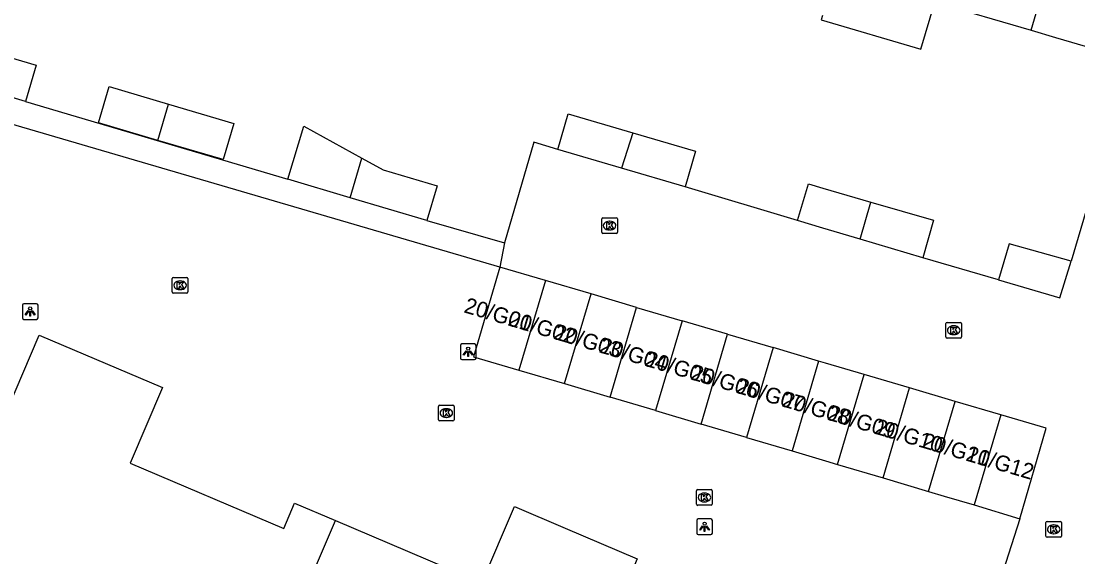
# Model space of a CAD drawing. Extents: x 161771 to 163125, y 382479 to 383177.
# Drawn here: x 162448.9 to 162516.2, y 382553 to 382587.1 of the extents above; entities that cross this region are included whole.
import ezdxf

# ---------------------------------------------------------------- set-up
doc = ezdxf.new("R2010")
doc.units = 0
for name, color, linetype in [('IMGEO_Kolk', 7, 'Continuous'), ('IMGEO_Lichtpunt', 7, 'Continuous'), ('IMGEO_Pand', 7, 'Continuous'), ('IMGEO_Pand_nummerreeks', 7, 'Continuous'), ('IMGEO_Voetpad_open', 7, 'Continuous')]:
    doc.layers.add(name, color=color, linetype=linetype)

msp = doc.modelspace()

# ---------------------------------------------------------------- linework, layer by layer
at = {"layer": 'IMGEO_Kolk'}
for p, q in [((162485.92, 382573.655), (162485.92, 382574.507)), ((162485.995, 382574.581), (162486.847, 382574.581)), ((162486.408, 382574.361), (162486.433, 382574.361)), ((162486.921, 382574.507), (162486.921, 382573.655)), ((162486.847, 382573.581), (162485.995, 382573.581)), ((162486.431, 382573.801), (162486.406, 382573.801)), ((162458.569, 382569.851), (162458.569, 382570.703)), ((162458.644, 382570.777), (162459.496, 382570.777)), ((162459.57, 382570.703), (162459.57, 382569.851)), ((162459.057, 382570.557), (162459.082, 382570.557)), ((162459.496, 382569.777), (162458.644, 382569.777)), ((162459.08, 382569.997), (162459.055, 382569.997)), ((162507.84, 382566.985), (162507.84, 382567.837)), ((162507.915, 382567.911), (162508.767, 382567.911)), ((162508.328, 382567.691), (162508.353, 382567.691)), ((162508.841, 382567.837), (162508.841, 382566.985)), ((162508.767, 382566.911), (162507.915, 382566.911)), ((162508.351, 382567.131), (162508.326, 382567.131)), ((162475.597, 382562.631), (162476.449, 382562.631)), ((162475.522, 382561.705), (162475.522, 382562.557)), ((162476.01, 382562.411), (162476.035, 382562.411)), ((162476.523, 382562.557), (162476.523, 382561.705)), ((162476.449, 382561.631), (162475.597, 382561.631)), ((162476.033, 382561.851), (162476.008, 382561.851)), ((162492.037, 382557.25), (162492.889, 382557.25)), ((162491.962, 382556.324), (162491.962, 382557.176)), ((162492.45, 382557.03), (162492.475, 382557.03)), ((162492.963, 382557.176), (162492.963, 382556.324)), ((162492.889, 382556.25), (162492.037, 382556.25)), ((162492.473, 382556.47), (162492.448, 382556.47)), ((162514.284, 382555.221), (162515.136, 382555.221)), ((162514.209, 382554.295), (162514.209, 382555.147)), ((162514.697, 382555.001), (162514.722, 382555.001)), ((162515.21, 382555.147), (162515.21, 382554.295)), ((162515.136, 382554.221), (162514.284, 382554.221)), ((162514.72, 382554.441), (162514.695, 382554.441))]:
    msp.add_line(p, q, dxfattribs=at)
for points in [[(162485.92, 382573.655), (162485.92, 382574.507)], [(162485.995, 382574.581), (162486.847, 382574.581)], [(162486.241, 382574.281), (162486.364, 382574.281), (162486.364, 382574.13), (162486.494, 382574.281), (162486.658, 382574.281), (162486.512, 382574.13), (162486.665, 382573.881), (162486.513, 382573.881), (162486.428, 382574.045), (162486.364, 382573.978), (162486.364, 382573.881), (162486.241, 382573.881), (162486.241, 382574.281)], [(162486.921, 382574.507), (162486.921, 382573.655)], [(162486.847, 382573.581), (162485.995, 382573.581)], [(162458.569, 382569.851), (162458.569, 382570.703)], [(162458.644, 382570.777), (162459.496, 382570.777)], [(162459.57, 382570.703), (162459.57, 382569.851)], [(162458.89, 382570.477), (162459.013, 382570.477), (162459.013, 382570.326), (162459.143, 382570.477), (162459.307, 382570.477), (162459.161, 382570.326), (162459.314, 382570.077), (162459.162, 382570.077), (162459.077, 382570.241), (162459.013, 382570.174), (162459.013, 382570.077), (162458.89, 382570.077), (162458.89, 382570.477)], [(162459.496, 382569.777), (162458.644, 382569.777)], [(162507.84, 382566.985), (162507.84, 382567.837)], [(162507.915, 382567.911), (162508.767, 382567.911)], [(162508.161, 382567.611), (162508.284, 382567.611), (162508.284, 382567.46), (162508.414, 382567.611), (162508.578, 382567.611), (162508.432, 382567.46), (162508.585, 382567.211), (162508.433, 382567.211), (162508.348, 382567.375), (162508.284, 382567.308), (162508.284, 382567.211), (162508.161, 382567.211), (162508.161, 382567.611)], [(162508.841, 382567.837), (162508.841, 382566.985)], [(162508.767, 382566.911), (162507.915, 382566.911)], [(162475.597, 382562.631), (162476.449, 382562.631)], [(162475.522, 382561.705), (162475.522, 382562.557)], [(162475.843, 382562.331), (162475.966, 382562.331), (162475.966, 382562.18), (162476.096, 382562.331), (162476.26, 382562.331), (162476.114, 382562.18), (162476.267, 382561.931), (162476.115, 382561.931), (162476.03, 382562.095), (162475.966, 382562.028), (162475.966, 382561.931), (162475.843, 382561.931), (162475.843, 382562.331)], [(162476.523, 382562.557), (162476.523, 382561.705)], [(162476.449, 382561.631), (162475.597, 382561.631)], [(162492.037, 382557.25), (162492.889, 382557.25)], [(162491.962, 382556.324), (162491.962, 382557.176)], [(162492.283, 382556.95), (162492.406, 382556.95), (162492.406, 382556.799), (162492.536, 382556.95), (162492.7, 382556.95), (162492.554, 382556.799), (162492.707, 382556.55), (162492.555, 382556.55), (162492.47, 382556.714), (162492.406, 382556.647), (162492.406, 382556.55), (162492.283, 382556.55), (162492.283, 382556.95)], [(162492.963, 382557.176), (162492.963, 382556.324)], [(162492.889, 382556.25), (162492.037, 382556.25)], [(162514.284, 382555.221), (162515.136, 382555.221)], [(162514.209, 382554.295), (162514.209, 382555.147)], [(162514.53, 382554.921), (162514.653, 382554.921), (162514.653, 382554.77), (162514.783, 382554.921), (162514.947, 382554.921), (162514.801, 382554.77), (162514.954, 382554.521), (162514.802, 382554.521), (162514.717, 382554.685), (162514.653, 382554.618), (162514.653, 382554.521), (162514.53, 382554.521), (162514.53, 382554.921)], [(162515.21, 382555.147), (162515.21, 382554.295)], [(162515.136, 382554.221), (162514.284, 382554.221)]]:
    msp.add_lwpolyline(points, dxfattribs=at)
for centre, start, end in [((162485.997, 382574.505), 91.55205, 178.44795), ((162485.997, 382574.505), 91.55205, 178.44795), ((162486.845, 382574.505), 1.55205, 88.44795), ((162486.845, 382574.505), 1.55205, 88.44795), ((162485.997, 382573.657), 181.55205, 268.44795), ((162485.997, 382573.657), 181.55205, 268.44795), ((162486.845, 382573.657), 271.55205, 358.44795), ((162486.845, 382573.657), 271.55205, 358.44795), ((162458.646, 382570.701), 91.55205, 178.44795), ((162458.646, 382570.701), 91.55205, 178.44795), ((162459.494, 382570.701), 1.55205, 88.44795), ((162459.494, 382570.701), 1.55205, 88.44795), ((162458.646, 382569.853), 181.55205, 268.44795), ((162458.646, 382569.853), 181.55205, 268.44795), ((162459.494, 382569.853), 271.55205, 358.44795), ((162459.494, 382569.853), 271.55205, 358.44795), ((162507.917, 382567.835), 91.55205, 178.44795), ((162507.917, 382567.835), 91.55205, 178.44795), ((162508.765, 382567.835), 1.55205, 88.44795), ((162508.765, 382567.835), 1.55205, 88.44795), ((162507.917, 382566.987), 181.55205, 268.44795), ((162507.917, 382566.987), 181.55205, 268.44795), ((162508.765, 382566.987), 271.55205, 358.44795), ((162508.765, 382566.987), 271.55205, 358.44795), ((162475.599, 382562.555), 91.55205, 178.44795), ((162475.599, 382562.555), 91.55205, 178.44795), ((162476.447, 382562.555), 1.55205, 88.44795), ((162476.447, 382562.555), 1.55205, 88.44795), ((162475.599, 382561.707), 181.55205, 268.44795), ((162475.599, 382561.707), 181.55205, 268.44795), ((162476.447, 382561.707), 271.55205, 358.44795), ((162476.447, 382561.707), 271.55205, 358.44795), ((162492.039, 382557.174), 91.55205, 178.44795), ((162492.039, 382557.174), 91.55205, 178.44795), ((162492.887, 382557.174), 1.55205, 88.44795), ((162492.887, 382557.174), 1.55205, 88.44795), ((162492.039, 382556.326), 181.55205, 268.44795), ((162492.039, 382556.326), 181.55205, 268.44795), ((162492.887, 382556.326), 271.55205, 358.44795), ((162492.887, 382556.326), 271.55205, 358.44795), ((162514.286, 382555.145), 91.55205, 178.44795), ((162514.286, 382555.145), 91.55205, 178.44795), ((162515.134, 382555.145), 1.55205, 88.44795), ((162515.134, 382555.145), 1.55205, 88.44795), ((162514.286, 382554.297), 181.55205, 268.44795), ((162514.286, 382554.297), 181.55205, 268.44795), ((162515.134, 382554.297), 271.55205, 358.44795), ((162515.134, 382554.297), 271.55205, 358.44795)]:
    msp.add_arc(centre, 0.0765, start, end, dxfattribs=at)
for centre, major_axis, ratio, start_param, end_param in [((162486.407, 382574.081), (-0.387, 0.002), 0.722429, 4.712389, 7.853982), ((162486.432, 382574.081), (-0.39, 0.002), 0.717154, 1.570796, 4.712389), ((162459.056, 382570.277), (-0.387, 0.002), 0.722429, 4.712389, 7.853982), ((162459.081, 382570.277), (-0.39, 0.002), 0.717154, 1.570796, 4.712389), ((162508.327, 382567.411), (-0.387, 0.002), 0.722429, 4.712389, 7.853982), ((162508.352, 382567.411), (-0.39, 0.002), 0.717154, 1.570796, 4.712389), ((162476.009, 382562.131), (-0.387, 0.002), 0.722429, 4.712389, 7.853982), ((162476.034, 382562.131), (-0.39, 0.002), 0.717154, 1.570796, 4.712389), ((162492.449, 382556.75), (-0.387, 0.002), 0.722429, 4.712389, 7.853982), ((162492.474, 382556.75), (-0.39, 0.002), 0.717154, 1.570796, 4.712389), ((162514.696, 382554.721), (-0.387, 0.002), 0.722429, 4.712389, 7.853982), ((162514.721, 382554.721), (-0.39, 0.002), 0.717154, 1.570796, 4.712389)]:
    msp.add_ellipse(centre, major_axis=major_axis, ratio=ratio, start_param=start_param, end_param=end_param, dxfattribs=at)
at = {"layer": 'IMGEO_Lichtpunt'}
for p, q in [((162449.023, 382569.006), (162449.023, 382568.199)), ((162449.023, 382569.006), (162449.023, 382568.199)), ((162449.925, 382569.101), (162449.117, 382569.101)), ((162449.925, 382569.101), (162449.117, 382569.101)), ((162450.019, 382568.199), (162450.019, 382569.006)), ((162450.019, 382568.199), (162450.019, 382569.006)), ((162449.117, 382568.105), (162449.925, 382568.105)), ((162449.117, 382568.105), (162449.925, 382568.105)), ((162476.92, 382566.441), (162476.92, 382565.634)), ((162476.92, 382566.441), (162476.92, 382565.634)), ((162477.822, 382566.536), (162477.014, 382566.536)), ((162477.822, 382566.536), (162477.014, 382566.536)), ((162477.916, 382565.634), (162477.916, 382566.441)), ((162477.916, 382565.634), (162477.916, 382566.441)), ((162477.014, 382565.54), (162477.822, 382565.54)), ((162477.014, 382565.54), (162477.822, 382565.54)), ((162491.972, 382555.287), (162491.972, 382554.48)), ((162491.972, 382555.287), (162491.972, 382554.48)), ((162492.874, 382555.382), (162492.066, 382555.382)), ((162492.874, 382555.382), (162492.066, 382555.382)), ((162492.968, 382554.48), (162492.968, 382555.287)), ((162492.968, 382554.48), (162492.968, 382555.287)), ((162492.066, 382554.386), (162492.874, 382554.386)), ((162492.066, 382554.386), (162492.874, 382554.386))]:
    msp.add_line(p, q, dxfattribs=at)
for points in [[(162449.397, 382568.67), (162449.436, 382568.642), (162449.248, 382568.38), (162449.21, 382568.407), (162449.397, 382568.67)], [(162449.499, 382568.622), (162449.546, 382568.622), (162449.546, 382568.3), (162449.499, 382568.3), (162449.499, 382568.622)], [(162449.609, 382568.642), (162449.647, 382568.669), (162449.834, 382568.407), (162449.795, 382568.379), (162449.609, 382568.642)], [(162477.294, 382566.105), (162477.333, 382566.077), (162477.145, 382565.815), (162477.107, 382565.842), (162477.294, 382566.105)], [(162477.396, 382566.057), (162477.443, 382566.057), (162477.443, 382565.735), (162477.396, 382565.735), (162477.396, 382566.057)], [(162477.506, 382566.077), (162477.544, 382566.104), (162477.731, 382565.842), (162477.692, 382565.814), (162477.506, 382566.077)], [(162492.346, 382554.951), (162492.385, 382554.923), (162492.197, 382554.661), (162492.159, 382554.688), (162492.346, 382554.951)], [(162492.448, 382554.903), (162492.495, 382554.903), (162492.495, 382554.581), (162492.448, 382554.581), (162492.448, 382554.903)], [(162492.558, 382554.923), (162492.596, 382554.95), (162492.783, 382554.688), (162492.744, 382554.66), (162492.558, 382554.923)]]:
    msp.add_lwpolyline(points, dxfattribs=at)
for centre in [(162449.522, 382568.804), (162477.419, 382566.239), (162492.471, 382555.085)]:
    msp.add_circle(centre, 0.0994, dxfattribs=at)
for centre, start, end in [((162449.117, 382569.006), 90, 180), ((162449.117, 382569.006), 90, 180), ((162449.925, 382569.006), 0, 90), ((162449.925, 382569.006), 0, 90), ((162449.117, 382568.199), 180, 270), ((162449.117, 382568.199), 180, 270), ((162449.925, 382568.199), 270, 0), ((162449.925, 382568.199), 270, 360), ((162477.014, 382566.441), 90, 180), ((162477.014, 382566.441), 90, 180), ((162477.822, 382566.441), 0, 90), ((162477.822, 382566.441), 0, 90), ((162477.014, 382565.634), 180, 270), ((162477.014, 382565.634), 180, 270), ((162477.822, 382565.634), 270, 0), ((162477.822, 382565.634), 270, 360), ((162492.066, 382555.287), 90, 180), ((162492.066, 382555.287), 90, 180), ((162492.874, 382555.287), 0, 90), ((162492.874, 382555.287), 0, 90), ((162492.066, 382554.48), 180, 270), ((162492.066, 382554.48), 180, 270), ((162492.874, 382554.48), 270, 0), ((162492.874, 382554.48), 270, 360)]:
    msp.add_arc(centre, 0.0946, start, end, dxfattribs=at)
at = {"layer": 'IMGEO_Pand'}
for points in [[(162513.27, 382586.527), (162515.548, 382594.26)], [(162499.972, 382587.47), (162499.891, 382587.195), (162506.251, 382585.323), (162507.137, 382588.332)], [(162507.137, 382588.332), (162513.27, 382586.527)], [(162513.27, 382586.527), (162514.821, 382586.07), (162519.617, 382584.659)], [(162445.105, 382583.214), (162445.786, 382585.524), (162449.901, 382584.31), (162449.219, 382581.999)], [(162449.219, 382581.999), (162445.105, 382583.214)], [(162457.649, 382579.512), (162453.863, 382580.629), (162454.545, 382582.94), (162458.331, 382581.822)], [(162458.331, 382581.822), (162462.495, 382580.593), (162461.814, 382578.283), (162457.649, 382579.512)], [(162457.649, 382579.512), (162458.331, 382581.822)], [(162483.122, 382578.939), (162483.791, 382581.207), (162487.9, 382579.994)], [(162465.935, 382577.029), (162466.944, 382580.427), (162470.647, 382578.383)], [(162487.9, 382579.994), (162487.173, 382577.743)], [(162487.9, 382579.994), (162491.899, 382578.814), (162491.23, 382576.546)], [(162487.173, 382577.743), (162483.122, 382578.939)], [(162469.898, 382575.851), (162470.647, 382578.383)], [(162470.647, 382578.383), (162472.001, 382577.636), (162475.434, 382576.617), (162474.776, 382574.402)], [(162491.23, 382576.546), (162487.173, 382577.743)], [(162469.898, 382575.851), (162465.935, 382577.029)], [(162498.393, 382574.396), (162499.085, 382576.732), (162500, 382576.466), (162503.067, 382575.574)], [(162474.776, 382574.402), (162469.898, 382575.851)], [(162502.372, 382573.21), (162503.067, 382575.574)], [(162503.067, 382575.574), (162507.047, 382574.417), (162506.373, 382572.017)], [(162502.372, 382573.21), (162500, 382573.917), (162498.393, 382574.396)], [(162506.373, 382572.017), (162502.372, 382573.21)], [(162515.824, 382571.805), (162511.868, 382572.919), (162511.188, 382570.626)], [(162479.442, 382571.437), (162478.027, 382566.642), (162477.755, 382565.721), (162480.652, 382564.863)], [(162482.341, 382570.581), (162479.442, 382571.437)], [(162511.188, 382570.626), (162515.105, 382569.472), (162515.824, 382571.805)], [(162482.341, 382570.581), (162480.652, 382564.863)], [(162485.24, 382569.725), (162482.341, 382570.581)], [(162483.551, 382564.005), (162485.24, 382569.725)], [(162488.139, 382568.868), (162485.24, 382569.725)], [(162486.449, 382563.147), (162488.139, 382568.868)], [(162488.139, 382568.868), (162491.038, 382568.012)], [(162431.057, 382562.867), (162433.486, 382568.571), (162448.082, 382562.355), (162450.099, 382567.09), (162457.939, 382563.752), (162455.89, 382558.94), (162465.676, 382554.773), (162466.362, 382556.385), (162468.969, 382555.275)], [(162491.038, 382568.012), (162489.348, 382562.289)], [(162493.937, 382567.156), (162491.038, 382568.012)], [(162492.246, 382561.431), (162493.937, 382567.156)], [(162493.937, 382567.156), (162496.836, 382566.3)], [(162496.836, 382566.3), (162495.145, 382560.573)], [(162499.735, 382565.444), (162496.836, 382566.3)], [(162499.735, 382565.444), (162498.043, 382559.715)], [(162502.634, 382564.587), (162500.167, 382565.316), (162499.735, 382565.444)], [(162480.652, 382564.863), (162483.551, 382564.005)], [(162483.551, 382564.005), (162486.449, 382563.147)], [(162500.942, 382558.857), (162502.634, 382564.587)], [(162505.533, 382563.731), (162502.634, 382564.587)], [(162503.84, 382557.999), (162505.533, 382563.731)], [(162508.432, 382562.875), (162505.533, 382563.731)], [(162489.348, 382562.289), (162486.449, 382563.147)], [(162506.738, 382557.141), (162508.432, 382562.875)], [(162511.331, 382562.018), (162508.432, 382562.875)], [(162489.348, 382562.289), (162492.246, 382561.431)], [(162511.331, 382562.018), (162509.637, 382556.284)], [(162512.541, 382555.383), (162514.23, 382561.162), (162511.331, 382562.018)], [(162495.145, 382560.573), (162492.246, 382561.431)], [(162495.145, 382560.573), (162498.043, 382559.715)], [(162498.043, 382559.715), (162500.167, 382559.086), (162500.942, 382558.857)], [(162500.942, 382558.857), (162503.84, 382557.999)], [(162503.84, 382557.999), (162506.738, 382557.141)], [(162506.738, 382557.141), (162507.741, 382556.844), (162509.637, 382556.284)], [(162468.969, 382555.275), (162478.286, 382551.307), (162480.358, 382556.171), (162483.588, 382554.796), (162488.188, 382552.837), (162487.561, 382551.364), (162508.291, 382542.509), (162505.539, 382533.532), (162502.883, 382534.282), (162502.196, 382532.679), (162499.067, 382534.004), (162498.39, 382532.406), (162484.994, 382538.139), (162484.309, 382536.517), (162480.038, 382538.321), (162479.345, 382536.736), (162463.859, 382543.342)], [(162509.637, 382556.284), (162512.541, 382555.383)], [(162463.859, 382543.342), (162468.969, 382555.275)]]:
    msp.add_lwpolyline(points, dxfattribs=at)
at = {"layer": 'IMGEO_Voetpad_open'}
for points in [[(162479.442, 382571.437), (162443.542, 382581.946), (162447.462, 382595.504), (162446.694, 382595.726), (162447.021, 382596.856)], [(162519.617, 382584.659), (162515.824, 382571.805)], [(162449.219, 382581.999), (162465.935, 382577.029)], [(162483.122, 382578.939), (162481.59, 382579.408), (162479.73, 382572.971)], [(162498.393, 382574.396), (162491.23, 382576.546)], [(162474.776, 382574.402), (162479.73, 382572.971)], [(162479.73, 382572.971), (162479.442, 382571.437)], [(162511.188, 382570.626), (162506.373, 382572.017)], [(162512.541, 382555.383), (162510.567, 382549.224), (162510.869, 382549.086)]]:
    msp.add_lwpolyline(points, dxfattribs=at)

# ---------------------------------------------------------------- texts
at = {"layer": 'IMGEO_Pand_nummerreeks'}
for s, p in [('20/G01', (162477.09, 382568.562)), ('20/G02', (162479.886, 382567.736)), ('20/G03', (162482.8, 382566.875)), ('20/G04', (162485.708, 382566.015)), ('20/G05', (162488.616, 382565.156)), ('20/G06', (162491.524, 382564.297)), ('20/G07', (162494.432, 382563.437)), ('20/G08', (162497.343, 382562.577)), ('20/G09', (162500.245, 382561.719)), ('20/G10', (162503.247, 382560.832)), ('20/G11', (162506.258, 382559.943)), ('20/G12', (162509.054, 382559.116))]:
    msp.add_text(s, height=1, rotation=343.53892, dxfattribs=at).set_placement(p)

doc.saveas('drawing.dxf')
